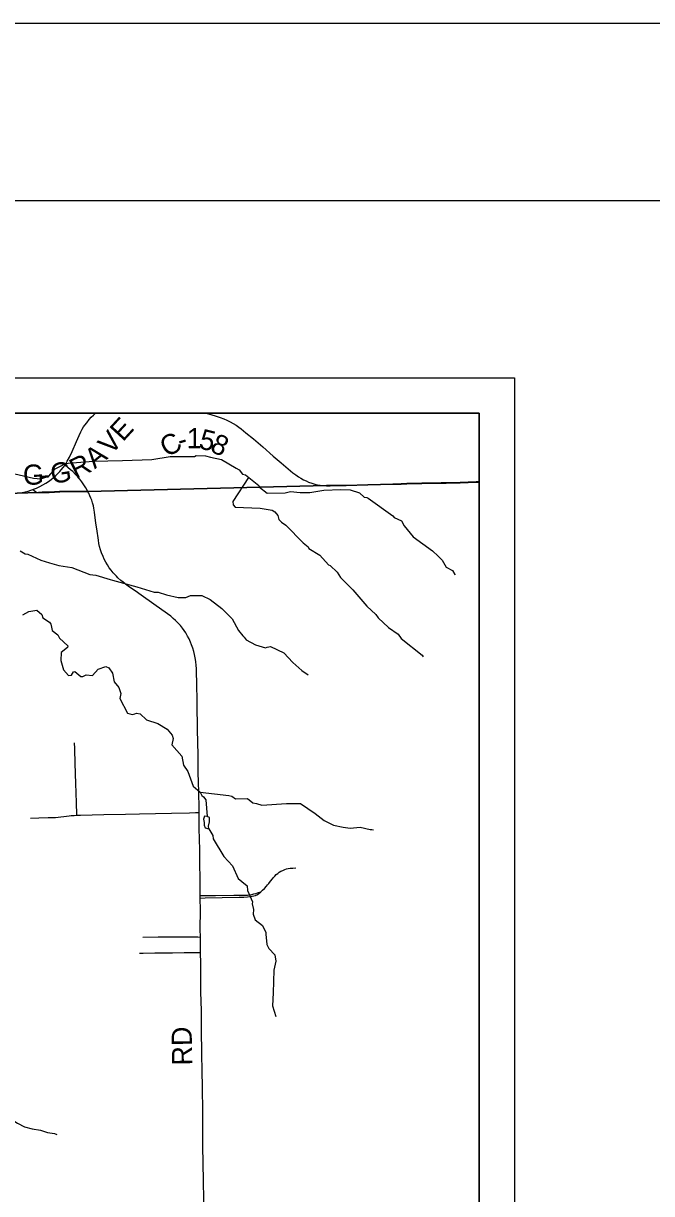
# Model space of a CAD drawing. Extents: x -6.4 to 34, y -4.2 to 22.
# Drawn here: x 7.614 to 9.387, y 18.698 to 22 of the extents above; entities that cross this region are included whole.
import ezdxf

# ---------------------------------------------------------------- set-up
doc = ezdxf.new("R2010")
doc.units = 0
for name, color, linetype in [('GM_X_Corporation', 7, 'Continuous'), ('GM_X_County_Road', 7, 'Continuous'), ('GM_X_County_Road_Text', 7, 'Continuous'), ('GM_X_Minor_Lake', 7, 'Continuous'), ('GM_X_Minor_River', 7, 'Continuous'), ('GM_X_Township_Road', 7, 'Continuous'), ('SH_Border', 7, 'Continuous'), ('SH_Cut_Line', 7, 'Continuous'), ('SH_Data', 7, 'Continuous')]:
    doc.layers.add(name, color=color, linetype=linetype)

msp = doc.modelspace()

# ---------------------------------------------------------------- linework, layer by layer
at = {"layer": 'GM_X_Corporation'}
for points in [[(7.5665, 20.6737), (7.6561, 20.6768), (7.6591, 20.6768), (7.6665, 20.677), (7.6863, 20.6775), (7.6956, 20.6777), (7.7018, 20.6779), (7.7162, 20.6789), (7.7958, 20.6792), (8.4694, 20.6962), (8.4793, 20.6959), (8.5246, 20.6966), (8.5861, 20.6984), (8.6569, 20.7002), (8.6799, 20.7009), (8.6961, 20.7014), (8.7383, 20.7025), (8.7932, 20.7035), (8.8001, 20.7036), (8.8069, 20.7037), (8.8464, 20.7045), (8.8918, 20.7063), (8.9, 20.7065), (8.9, 20.9), (6.9491, 20.9)], [(8.9, 15.9356), (8.9, 20.7065), (8.8918, 20.7063), (8.8464, 20.7045), (8.8069, 20.7037), (8.8001, 20.7036), (8.7932, 20.7035), (8.7383, 20.7025), (8.6961, 20.7014), (8.6799, 20.7009), (8.6569, 20.7002), (8.5861, 20.6984), (8.5246, 20.6966), (8.4793, 20.6959), (8.4694, 20.6962), (7.7958, 20.6792), (7.7162, 20.6789), (7.7018, 20.6779), (7.6956, 20.6777), (7.6863, 20.6775), (7.6665, 20.677), (7.6591, 20.6768), (7.6561, 20.6768), (7.5665, 20.6737)]]:
    msp.add_lwpolyline(points, dxfattribs=at)
at = {"layer": 'GM_X_County_Road'}
for points in [[(7.7316, 20.754), (7.7374, 20.7644), (7.7437, 20.7765), (7.7511, 20.7922), (7.7636, 20.8206), (7.7709, 20.8371), (7.7761, 20.8477), (7.7802, 20.8554), (7.7838, 20.8613), (7.7877, 20.8669), (7.7927, 20.8734), (7.7998, 20.8821), (7.8056, 20.8886), (7.8118, 20.8948), (7.8177, 20.9)], [(8.1284, 20.9), (8.1359, 20.898), (8.1547, 20.8926), (8.1605, 20.891), (8.1688, 20.8882), (8.1793, 20.8842), (8.1884, 20.8803), (8.1974, 20.8759), (8.2062, 20.8712), (8.2147, 20.866), (8.222, 20.8611), (8.2289, 20.8558), (8.242, 20.8452), (8.2629, 20.8276), (8.2894, 20.8049), (8.3188, 20.7791), (8.3416, 20.7598), (8.3745, 20.7324), (8.3829, 20.726), (8.3899, 20.721), (8.3968, 20.7168), (8.4043, 20.7126), (8.4116, 20.7091), (8.419, 20.706), (8.4277, 20.7029), (8.436, 20.7004), (8.4438, 20.6985), (8.4517, 20.6972), (8.4615, 20.6961), (8.4696, 20.6956)], [(7.5667, 20.6731), (7.5936, 20.6747), (7.6046, 20.6759), (7.6107, 20.6767), (7.6185, 20.6783), (7.6269, 20.6804), (7.6351, 20.6829), (7.6408, 20.6849), (7.6426, 20.6856), (7.6506, 20.6889), (7.6606, 20.6935), (7.6688, 20.6978), (7.6768, 20.7025), (7.6845, 20.7075), (7.6919, 20.713), (7.6991, 20.7188), (7.7055, 20.7246), (7.7111, 20.7302), (7.7165, 20.7361), (7.7253, 20.7462), (7.7316, 20.754)], [(7.796, 20.6787), (7.7945, 20.6814), (7.7897, 20.69), (7.7844, 20.6984), (7.7788, 20.7065), (7.7732, 20.7138), (7.7672, 20.7208), (7.7609, 20.7276), (7.753, 20.7354), (7.747, 20.7407), (7.7316, 20.754)], [(8.4696, 20.6956), (8.4795, 20.6954), (8.5248, 20.696), (8.5863, 20.6978), (8.6571, 20.6996), (8.6801, 20.7004), (8.6963, 20.7008), (8.7385, 20.7019), (8.7934, 20.7029), (8.8003, 20.703), (8.8071, 20.7031), (8.8466, 20.7039), (8.892, 20.7057), (8.9, 20.7059)], [(7.6408, 20.6849), (7.6477, 20.6795), (7.6491, 20.6784), (7.6508, 20.6775), (7.6531, 20.6767), (7.6563, 20.6763)], [(7.6563, 20.6763), (7.6593, 20.6762), (7.6667, 20.6765), (7.6865, 20.6769), (7.6958, 20.6772), (7.702, 20.6773), (7.7164, 20.6784)], [(8.1242, 18.6293), (8.1222, 18.7343), (8.1207, 18.8335), (8.1202, 18.9286), (8.1194, 18.9988), (8.1186, 19.0448), (8.1178, 19.0914), (8.1169, 19.1623), (8.1163, 19.2139), (8.1151, 19.268), (8.1146, 19.3208), (8.1145, 19.3476), (8.114, 19.3787), (8.1137, 19.422), (8.1132, 19.4445), (8.1133, 19.498), (8.1131, 19.5322), (8.1131, 19.539), (8.1126, 19.575), (8.1119, 19.6409), (8.1114, 19.6701), (8.1109, 19.6968), (8.1104, 19.7304), (8.11, 19.749), (8.1097, 19.7739), (8.1096, 19.7863), (8.1087, 19.8298), (8.1082, 19.8603), (8.1076, 19.8857), (8.1068, 19.9367), (8.1053, 20.0069), (8.1051, 20.0267), (8.1046, 20.0616), (8.104, 20.0957), (8.1034, 20.128), (8.1022, 20.1795), (8.1016, 20.1888), (8.1005, 20.1992), (8.0989, 20.2096), (8.097, 20.2192), (8.0948, 20.2282), (8.092, 20.2376), (8.0887, 20.2469), (8.0857, 20.2543), (8.0816, 20.2633), (8.0774, 20.2715), (8.0725, 20.2801), (8.0678, 20.2872), (8.0627, 20.2941), (8.0572, 20.3008), (8.0496, 20.3089), (8.0431, 20.3155), (8.0368, 20.3213), (8.0297, 20.3272), (8.0208, 20.3339), (7.9823, 20.3613), (7.9464, 20.3869), (7.9296, 20.3987), (7.9136, 20.4095), (7.9024, 20.4175), (7.9, 20.4195), (7.896, 20.4226), (7.8951, 20.4234), (7.8889, 20.4286), (7.8808, 20.4356), (7.8762, 20.4407), (7.8677, 20.4499), (7.8617, 20.4572), (7.8564, 20.4642), (7.8512, 20.472), (7.8463, 20.4801), (7.8422, 20.4879), (7.8386, 20.4959), (7.8347, 20.5059), (7.8317, 20.5148), (7.8291, 20.5238), (7.827, 20.533), (7.8254, 20.5423), (7.821, 20.5737), (7.8187, 20.5903), (7.8148, 20.6205), (7.813, 20.6321), (7.8115, 20.6393), (7.8093, 20.647), (7.8066, 20.6545), (7.804, 20.6609), (7.8016, 20.6671), (7.7982, 20.6743), (7.796, 20.6787)]]:
    msp.add_lwpolyline(points, dxfattribs=at)
at = {"layer": 'GM_X_Minor_Lake'}
msp.add_line((8.123, 19.7496), (8.1242, 19.7451), dxfattribs=at)
msp.add_lwpolyline([(8.1242, 19.7451), (8.124, 19.7379), (8.1271, 19.7304), (8.1374, 19.7275), (8.1365, 19.7351), (8.1394, 19.7473), (8.1392, 19.7598), (8.1323, 19.7623), (8.1247, 19.763), (8.1222, 19.7549), (8.123, 19.7496)], dxfattribs=at)
at = {"layer": 'GM_X_Minor_River'}
for points in [[(7.5898, 20.7293), (7.6427, 20.7169), (7.6635, 20.7153), (7.6854, 20.7226), (7.7032, 20.743), (7.7239, 20.754), (7.7291, 20.7582), (7.8104, 20.7653), (7.8933, 20.7671), (7.9766, 20.7697), (8.028, 20.7782), (8.064, 20.7777), (8.0969, 20.7783), (8.1018, 20.7806), (8.1276, 20.7799), (8.1416, 20.7764), (8.1732, 20.7693), (8.2141, 20.7454), (8.2225, 20.7406), (8.2322, 20.7286), (8.2405, 20.7261), (8.2782, 20.696), (8.2801, 20.6918), (8.3016, 20.6747), (8.3527, 20.6752), (8.3682, 20.6797), (8.3951, 20.6764), (8.4228, 20.6768), (8.4617, 20.6828), (8.5097, 20.6852), (8.5366, 20.6838), (8.5625, 20.6751), (8.576, 20.6636), (8.5828, 20.6625), (8.5874, 20.6603), (8.6568, 20.6103), (8.6602, 20.6058), (8.6812, 20.5963), (8.689, 20.5823), (8.7141, 20.5513)], [(8.2492, 20.7191), (8.2054, 20.651), (8.2059, 20.6416), (8.2113, 20.6352), (8.2822, 20.6323), (8.3156, 20.6264), (8.3237, 20.6223), (8.3322, 20.6115), (8.335, 20.6005), (8.3423, 20.593), (8.3546, 20.5845), (8.4035, 20.5345), (8.418, 20.5234), (8.4196, 20.5181), (8.4502, 20.4992), (8.4749, 20.4727), (8.4799, 20.4709), (8.4995, 20.4515), (8.5092, 20.4365), (8.5439, 20.4021), (8.5836, 20.3557), (8.6082, 20.3326), (8.6152, 20.3225), (8.6444, 20.2953), (8.672, 20.2764), (8.6805, 20.2648), (8.7392, 20.2179), (8.7423, 20.2127)], [(8.7141, 20.5513), (8.7686, 20.5123), (8.7843, 20.497), (8.7963, 20.4851), (8.8072, 20.4659), (8.8248, 20.456), (8.8314, 20.4451), (8.8333, 20.4462)], [(7.6043, 20.5123), (7.6185, 20.5031), (7.6268, 20.5021), (7.6631, 20.4852), (7.6874, 20.478), (7.7137, 20.4705), (7.7501, 20.4651), (7.7677, 20.4581), (7.8012, 20.4451), (7.8179, 20.4434), (7.8586, 20.4312), (7.8651, 20.4294), (7.9336, 20.4101), (7.9827, 20.395), (7.9944, 20.3949), (8.0176, 20.388), (8.0503, 20.3806), (8.0727, 20.3803), (8.0851, 20.3858), (8.0942, 20.3856), (8.1173, 20.3856), (8.1413, 20.375), (8.1736, 20.349), (8.2028, 20.3203), (8.2208, 20.2875), (8.2331, 20.2722), (8.2366, 20.2681), (8.2431, 20.261), (8.2688, 20.2462), (8.2973, 20.2384), (8.3022, 20.2403), (8.3116, 20.2424), (8.349, 20.2245), (8.3745, 20.1972), (8.3995, 20.1741), (8.4178, 20.1619)], [(7.6122, 20.3313), (7.6291, 20.3407), (7.6517, 20.3441), (7.6659, 20.3326), (7.6684, 20.3232), (7.6879, 20.3106), (7.6914, 20.3053), (7.6926, 20.3012), (7.6955, 20.2875), (7.7108, 20.2749), (7.7155, 20.2651), (7.7393, 20.2435), (7.7379, 20.2389), (7.7203, 20.2249), (7.7199, 20.2029), (7.7268, 20.1764), (7.7407, 20.1603), (7.7498, 20.1613), (7.7549, 20.1701), (7.7591, 20.1717), (7.7756, 20.1571), (7.7816, 20.1569), (7.7869, 20.1604), (7.7914, 20.1624), (7.8089, 20.16), (7.8252, 20.1781), (7.8463, 20.1853), (7.8547, 20.1821), (7.8656, 20.1663), (7.8701, 20.1421), (7.8836, 20.1264), (7.8892, 20.109), (7.886, 20.0956), (7.9079, 20.0535), (7.9212, 20.0499), (7.9288, 20.0519), (7.9333, 20.0539), (7.9439, 20.0522), (7.9616, 20.0347), (7.9936, 20.0246), (8.0196, 20.0091), (8.0335, 19.9915), (8.0363, 19.9824), (8.0332, 19.9641), (8.0606, 19.9327), (8.0659, 19.9074), (8.078, 19.8894), (8.093, 19.8479), (8.113, 19.8311), (8.1177, 19.8217), (8.1219, 19.818), (8.1285, 19.8094), (8.1323, 19.7623)], [(8.113, 19.8311), (8.1934, 19.8219), (8.2026, 19.8198), (8.2125, 19.8123), (8.2462, 19.8133), (8.2616, 19.8011), (8.2715, 19.7986), (8.2867, 19.7947), (8.3563, 19.7993), (8.3964, 19.7992), (8.437, 19.7711), (8.4631, 19.7514), (8.4894, 19.7382), (8.5168, 19.7322), (8.5366, 19.7295), (8.5642, 19.7319), (8.5923, 19.7259), (8.5972, 19.7253), (8.6018, 19.7242)], [(8.1374, 19.7275), (8.1483, 19.7091), (8.1492, 19.6992), (8.1792, 19.6492), (8.2039, 19.6227), (8.2203, 19.5873), (8.2303, 19.5791), (8.2453, 19.5669), (8.2466, 19.5532), (8.2608, 19.5212), (8.2594, 19.5155), (8.263, 19.5003), (8.2621, 19.4863), (8.2677, 19.4712), (8.2888, 19.4545), (8.2982, 19.4349), (8.2982, 19.4303), (8.301, 19.4015), (8.3069, 19.3895), (8.3238, 19.3719), (8.3264, 19.3541), (8.3207, 19.329), (8.3191, 19.2644), (8.3174, 19.2279), (8.3266, 19.198)], [(7.4074, 19.1498), (7.4274, 19.1307), (7.447, 19.1166), (7.4678, 19.1096), (7.4871, 19.1084), (7.496, 19.0894), (7.5137, 19.0703), (7.5291, 19.0508), (7.5339, 19.0307), (7.5364, 19.0117), (7.5416, 18.9919), (7.5468, 18.9725), (7.5565, 18.9527), (7.5677, 18.9314), (7.5763, 18.9105), (7.5974, 18.8971), (7.6167, 18.8871), (7.6382, 18.8806), (7.662, 18.877), (7.6821, 18.8709), (7.7017, 18.8678), (7.7081, 18.8647)]]:
    msp.add_lwpolyline(points, dxfattribs=at)
at = {"layer": 'GM_X_Township_Road'}
for points in [[(7.7645, 19.7657), (7.7643, 19.7721), (7.7636, 19.797), (7.7624, 19.8324), (7.762, 19.8516), (7.7608, 19.8864), (7.7602, 19.9101), (7.759, 19.9542), (7.7584, 19.9703)], [(7.6338, 19.758), (7.6572, 19.7584), (7.6835, 19.7591), (7.7049, 19.7598), (7.7434, 19.7639), (7.7489, 19.7647), (7.7568, 19.7654), (7.7645, 19.7657), (7.7754, 19.7661), (7.8407, 19.7677), (7.9022, 19.7691), (7.9414, 19.7696), (8.0315, 19.7718), (8.083, 19.7731), (8.0992, 19.7736), (8.1097, 19.7739)], [(8.2841, 19.5499), (8.2892, 19.5543), (8.2945, 19.5594), (8.2999, 19.5653), (8.3031, 19.5692), (8.3066, 19.5735), (8.3116, 19.5798), (8.3167, 19.5862), (8.3201, 19.5902), (8.3232, 19.5937), (8.3276, 19.5982), (8.3318, 19.6019), (8.3359, 19.6049), (8.3402, 19.6076), (8.3458, 19.6103), (8.3516, 19.6127), (8.3564, 19.6143), (8.3613, 19.6155), (8.3664, 19.6163), (8.3744, 19.6169), (8.3825, 19.617)], [(8.1131, 19.5322), (8.1265, 19.5328), (8.223, 19.5348), (8.2363, 19.5351), (8.2467, 19.5357), (8.2537, 19.5363), (8.2593, 19.5371), (8.2644, 19.5382), (8.2688, 19.5397), (8.2731, 19.5417), (8.2775, 19.5441), (8.2841, 19.5499)], [(8.1131, 19.539), (8.126, 19.5392), (8.1563, 19.5394), (8.2081, 19.5403), (8.233, 19.5406), (8.2461, 19.5408), (8.2535, 19.5415), (8.259, 19.5424), (8.2645, 19.5437), (8.2698, 19.5454), (8.2742, 19.5471), (8.2841, 19.5499)], [(7.9509, 19.4222), (7.9944, 19.4225), (8.0162, 19.4227), (8.0386, 19.4227), (8.0634, 19.4228), (8.071, 19.4228), (8.0789, 19.4228), (8.0877, 19.4228), (8.0945, 19.4228), (8.1062, 19.4223), (8.1137, 19.422)], [(7.9411, 19.3767), (7.9516, 19.3768), (7.9852, 19.3772), (8.0088, 19.3776), (8.0349, 19.378), (8.0672, 19.3785), (8.107, 19.3787), (8.114, 19.3787)]]:
    msp.add_lwpolyline(points, dxfattribs=at)
at = {"layer": 'SH_Border'}
msp.add_lwpolyline([(1.5, 21.5), (33.5, 21.5), (33.5, 0.5), (1.5, 0.5)], close=True, dxfattribs=at)
at = {"layer": 'SH_Cut_Line'}
msp.add_lwpolyline([(0, 0), (34, 0), (34, 22), (0, 22)], close=True, dxfattribs=at)
at = {"layer": 'SH_Data'}
for p, q in [((2, 21), (9, 21)), ((9, 21), (9, 14)), ((2.1, 20.9), (8.9, 20.9)), ((8.9, 20.9), (8.9, 14.1))]:
    msp.add_line(p, q, dxfattribs=at)

# ---------------------------------------------------------------- texts
at = {"layer": 'GM_X_County_Road_Text'}
for s, height, rotation, p in [('E', 0.0568, 47.425, (7.8947, 20.8179)), ('V', 0.0568, 48.8895, (7.8621, 20.7805)), ('C', 0.0568, 29.3169, (8.0192, 20.7744)), ('1', 0.0568, 359.4275, (8.0749, 20.8016)), ('5', 0.0568, 346.0887, (8.1064, 20.8017)), ('8', 0.0568, 334.4892, (8.1376, 20.7943)), ('A', 0.0568, 38.9766, (7.8155, 20.7416)), ('-', 0.0568, 15.5036, (8.0566, 20.7959)), ('R', 0.0568, 25.8218, (7.7615, 20.7136)), ('G', 0.0568, 1.1642, (7.6131, 20.6979)), ('G', 0.0568, 8.9957, (7.6948, 20.7004)), ('-', 0.0568, 1.7837, (7.6637, 20.6989)), ('RD', 0.05682, 90.9872, (8.0906, 19.0602))]:
    msp.add_text(s, height=height, rotation=rotation, dxfattribs=at).set_placement(p)

doc.saveas('drawing.dxf')
